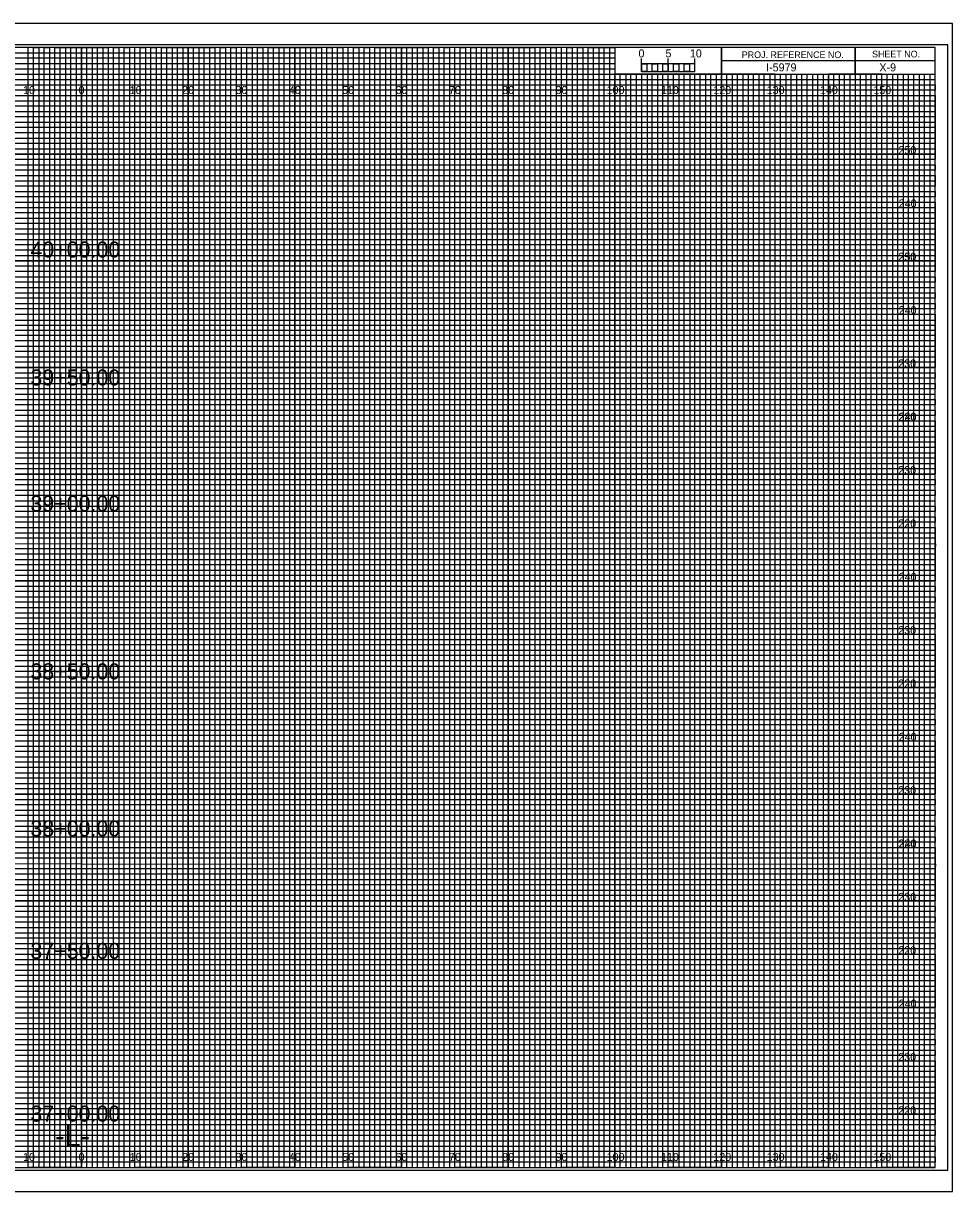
# Model space of a CAD drawing. Extents: x -13 to 359, y -5 to 2854.
# Drawn here: x 149.1 to 323.3, y 1755.5 to 1974.5 of the extents above; entities that cross this region are included whole.
import ezdxf

# ---------------------------------------------------------------- set-up
doc = ezdxf.new("R2010")
doc.units = 0
for name, color, linetype in [('Exist CMT Pavement', 7, 'Continuous'), ('Exist Cross Section Cell', 7, 'Continuous'), ('Exist XS Ground Line', 7, 'Continuous'), ('Prop CMT Conc Surface', 7, 'Continuous'), ('Prop CMT Concrete Structures', 7, 'Continuous'), ('Prop CMT DNC', 7, 'Continuous'), ('Prop CMT Pvmt Course 1', 7, 'Continuous'), ('Prop CMT Pvmt Course 1 CG', 7, 'Continuous'), ('Prop CMT Pvmt Course 1 Wedge', 7, 'Continuous'), ('Prop CMT Pvmt Course 2', 7, 'Continuous'), ('Prop CMT Pvmt Course 2 Wedge', 7, 'Continuous'), ('Prop CMT Pvmt Course 3', 7, 'Continuous'), ('Prop CMT Pvmt Course 3 Wedge', 7, 'Continuous'), ('Prop CMT Shear Line', 7, 'Continuous'), ('Prop CMT Slope Grass', 7, 'Continuous'), ('Prop CMT Subgrade Earthwork', 7, 'Continuous'), ('Scratch_Level_0', 7, 'Continuous')]:
    doc.layers.add(name, color=color, linetype=linetype)

msp = doc.modelspace()

# ---------------------------------------------------------------- linework, layer by layer
at = {"layer": 'Exist XS Ground Line'}
for p, q in [((150, 1970), (140, 1970)), ((150, 1760), (150, 1970)), ((170, 1970), (160, 1970)), ((160, 1970), (160, 1760)), ((170, 1760), (170, 1970)), ((190, 1970), (180, 1970)), ((180, 1970), (180, 1760)), ((190, 1760), (190, 1970)), ((210, 1970), (200, 1970)), ((200, 1970), (200, 1760)), ((210, 1760), (210, 1970)), ((230, 1970), (220, 1970)), ((220, 1970), (220, 1760)), ((230, 1760), (230, 1970)), ((250, 1970), (240, 1970)), ((240, 1970), (240, 1760)), ((250, 1760), (250, 1970)), ((260, 1970), (260, 1760)), ((270, 1760), (270, 1965)), ((290, 1965), (280, 1965)), ((280, 1965), (280, 1760)), ((290, 1760), (290, 1965)), ((310, 1965), (300, 1965)), ((300, 1965), (300, 1760)), ((310, 1760), (310, 1965)), ((160, 1760), (150, 1760)), ((180, 1760), (170, 1760)), ((200, 1760), (190, 1760)), ((220, 1760), (210, 1760)), ((240, 1760), (230, 1760)), ((260, 1760), (250, 1760)), ((280, 1760), (270, 1760)), ((300, 1760), (290, 1760)), ((320, 1760), (310, 1760)), ((320, 1760), (320, 1760))]:
    msp.add_line(p, q, dxfattribs=at)
for points in [[(0, 1960), (320, 1960), (320, 1950), (0, 1950)], [(0, 1940), (320, 1940), (320, 1930), (0, 1930)], [(0, 1920), (320, 1920), (320, 1910), (0, 1910)], [(0, 1900), (320, 1900), (320, 1890), (0, 1890)], [(0, 1880), (320, 1880), (320, 1870), (0, 1870)], [(0, 1860), (320, 1860), (320, 1850), (0, 1850)], [(0, 1840), (320, 1840), (320, 1830), (0, 1830)], [(0, 1820), (320, 1820), (320, 1810), (0, 1810)], [(0, 1800), (320, 1800), (320, 1790), (0, 1790)], [(0, 1780), (320, 1780), (320, 1770), (0, 1770)]]:
    msp.add_lwpolyline(points, dxfattribs=at)
at = {"layer": 'Prop CMT Conc Surface'}
for p, q in [((265, 1965.49), (265, 1967.9)), ((265, 1966.9), (265, 1967.9)), ((270, 1965.49), (270, 1967.9)), ((275, 1965.49), (275, 1967.9)), ((275, 1966.9), (275, 1967.9))]:
    msp.add_line(p, q, dxfattribs=at)
for points in [[(275, 1966.9), (265, 1966.9), (265, 1965.49), (275, 1965.49)], [(265, 1966.9), (266, 1966.9), (266, 1965.49), (265, 1965.49)], [(267, 1966.9), (268, 1966.9), (268, 1965.49), (267, 1965.49)], [(269, 1966.9), (270, 1966.9), (270, 1965.49), (269, 1965.49)], [(271, 1966.9), (272, 1966.9), (272, 1965.49), (271, 1965.49)], [(273, 1966.9), (274, 1966.9), (274, 1965.49), (273, 1965.49)]]:
    msp.add_lwpolyline(points, close=True, dxfattribs=at)
at = {"layer": 'Prop CMT Concrete Structures'}
for p, q in [((305, 1970), (305, 1965)), ((305, 1965), (305, 1970)), ((280, 1967.5), (280, 1965)), ((320, 1967.49), (280, 1967.49)), ((280, 1965), (320, 1965))]:
    msp.add_line(p, q, dxfattribs=at)
for points in [[(320, 1970), (0, 1970), (0, 1760), (320, 1760)], [(280, 1970), (260, 1970), (260, 1965.03), (280, 1965.03)], [(320, 1970), (280, 1970), (280, 1965), (320, 1965)]]:
    msp.add_lwpolyline(points, close=True, dxfattribs=at)
at = {"layer": 'Prop CMT DNC'}
for p, q in [((323.3, 1974.5), (-13.4, 1974.5)), ((-13.4, 1755.5), (323.3, 1755.5))]:
    msp.add_line(p, q, dxfattribs=at)
at = {"layer": 'Prop CMT Pvmt Course 1'}
for p, q in [((0, 1969), (260, 1969)), ((260, 1969), (260, 1967.98)), ((260, 1967.98), (0, 1967.98)), ((0, 1967), (260, 1967)), ((260, 1967), (260, 1965.89)), ((260, 1965.89), (0, 1965.89)), ((0, 1964), (320, 1964))]:
    msp.add_line(p, q, dxfattribs=at)
for points in [[(0, 1963), (270, 1963), (320, 1963), (320, 1962), (0, 1962)], [(0, 1961), (320, 1961), (320, 1959), (0, 1959)], [(0, 1958), (320, 1958), (320, 1957), (0, 1956.98)], [(0, 1956), (320, 1956), (320, 1954), (0, 1954)], [(0, 1953), (320, 1953), (320, 1952), (0, 1952)], [(0, 1951), (320, 1951), (320, 1949), (0, 1949)], [(0, 1948), (320, 1948), (320, 1947), (0, 1947)], [(0, 1946), (320, 1946), (320, 1944), (0, 1944)], [(0, 1943), (320, 1943), (320, 1942), (0, 1942)], [(0, 1941), (320, 1941), (320, 1939), (0, 1939)], [(0, 1938), (320, 1938), (320, 1937), (0, 1937)], [(0, 1936), (320, 1936), (320, 1933.95), (320, 1933), (320, 1932), (0, 1932)], [(0, 1934), (320, 1934), (320, 1933), (0, 1933)], [(0, 1931), (320, 1931), (320, 1929), (0, 1929.03)], [(0, 1929.03), (320, 1929), (320, 1928), (0, 1928)], [(0, 1927), (320, 1927), (320, 1926), (0, 1926)], [(0, 1924), (320, 1924), (320, 1923), (0, 1923)], [(0, 1922), (320, 1922), (320, 1921), (0, 1921)], [(-0.07, 1918.89), (320, 1918.89), (320, 1917.88), (-0.07, 1917.88)], [(0, 1917), (320, 1917), (320, 1916), (0, 1916)], [(0, 1914), (320, 1914), (320, 1913), (0, 1913)], [(0, 1912), (320, 1912), (320, 1911), (0, 1911)], [(0, 1909), (320, 1909), (320, 1908), (0, 1908)], [(0, 1907), (320, 1907), (320, 1906), (0, 1906)], [(0, 1904), (320, 1904), (320, 1903), (0, 1903)], [(0, 1902), (320, 1902), (320, 1901), (0, 1901)], [(0, 1899), (320, 1899), (319.99, 1897.98), (0, 1898)], [(0, 1897), (320, 1897), (320, 1896), (0, 1896)], [(0, 1894), (320, 1894), (320, 1893), (0, 1893)], [(0, 1892), (320, 1892), (320, 1891), (0, 1891)], [(0, 1889), (320, 1889), (320, 1888), (0, 1888)], [(0, 1887), (320, 1887), (320, 1886), (0, 1886)], [(0, 1884), (320, 1884), (320, 1883), (0, 1883)], [(0, 1882), (320, 1882), (320, 1881), (0, 1881)], [(0, 1879), (320, 1879), (320, 1878), (0, 1878)], [(0, 1876.99), (320.07, 1876.91), (320, 1876), (0, 1876)], [(0, 1874), (320, 1874), (320, 1873), (0, 1873)], [(0, 1872), (320, 1872), (320, 1871), (0, 1871)], [(0, 1869), (320, 1869), (320, 1868), (0, 1868)], [(0, 1867), (320, 1867), (320, 1866), (0, 1866)], [(0, 1864), (320, 1864), (320, 1863), (0, 1863)], [(0, 1862), (320, 1862), (320, 1861), (0, 1861)], [(0, 1859), (320, 1859), (320, 1858), (0, 1858)], [(0, 1857), (320, 1857), (320, 1856), (0, 1856)], [(0, 1854), (320, 1854), (320, 1853), (0, 1853)], [(0, 1852), (320, 1852), (320, 1851), (0, 1851)], [(0, 1849), (320, 1849), (320, 1848), (0, 1848)], [(0, 1847), (320, 1847), (320, 1846), (0, 1846)], [(0, 1844), (320, 1844), (320, 1843), (0, 1843)], [(0, 1842), (320, 1842), (320, 1841), (0, 1841)], [(0, 1839), (320, 1839), (319.99, 1837.98), (0, 1838)], [(0, 1837), (320, 1837), (320, 1836), (0, 1836)], [(0, 1834), (320, 1834), (320, 1833), (0, 1833)], [(0, 1832), (320, 1832), (320, 1831), (0, 1831)], [(0, 1829), (320, 1829), (320, 1828), (0, 1828)], [(0, 1827), (320, 1827), (320, 1826), (0, 1826)], [(0, 1824), (320, 1824), (320, 1823), (0, 1823)], [(0, 1822), (320, 1822), (320, 1821), (0, 1821)], [(0, 1819), (320, 1819), (320, 1818), (0, 1818)], [(0, 1816.99), (320.07, 1816.91), (320, 1816), (0, 1816)], [(0, 1814), (320, 1814), (320, 1813), (0, 1813)], [(0, 1812), (320, 1812), (320, 1811), (0, 1811)], [(0, 1809), (320, 1809), (320, 1808), (0, 1808)], [(0, 1807), (320, 1807), (320, 1806), (0, 1806)], [(0, 1804), (320, 1804), (320, 1803), (0, 1803)], [(0, 1802), (320, 1802), (320, 1801), (0, 1801)], [(0, 1799), (320, 1799), (320, 1798), (0, 1798)], [(0, 1797), (320, 1797), (320, 1796), (0, 1796)], [(0, 1794), (320, 1794), (320, 1793), (0, 1793)], [(0, 1792), (320, 1792), (320, 1791), (0, 1791)], [(0, 1789), (320, 1789), (320, 1788), (0, 1788)], [(0, 1787), (320, 1787), (320, 1786), (0, 1786)], [(0, 1784), (320, 1784), (320, 1783), (0, 1783)], [(0, 1782), (320, 1782), (320, 1781), (0, 1781)], [(0, 1779), (320, 1779), (320, 1778), (0, 1778)], [(0, 1777), (320, 1777), (320, 1776), (0, 1776)], [(0, 1774), (320, 1774), (320, 1773), (0, 1773)], [(0, 1772), (320, 1772), (320, 1771), (0, 1771)], [(0, 1769), (320, 1769), (320, 1768), (0, 1768)], [(0, 1767), (320, 1767), (320, 1766), (0, 1766)], [(0, 1764), (320, 1764), (320, 1763), (0, 1763)], [(0, 1762), (320, 1762), (320, 1761), (0, 1761)]]:
    msp.add_lwpolyline(points, dxfattribs=at)
at = {"layer": 'Prop CMT Pvmt Course 1 CG'}
for p, q in [((267, 1965), (266.01, 1965)), ((266.01, 1965), (266.01, 1760)), ((267, 1760), (267, 1965)), ((269, 1965), (268, 1965)), ((268, 1965), (268, 1760)), ((269, 1760), (269, 1965)), ((266.01, 1760), (265, 1760)), ((268, 1760), (267, 1760))]:
    msp.add_line(p, q, dxfattribs=at)
for points in [[(150, 1760), (151, 1760), (151, 1970), (152, 1970), (152, 1760)], [(152, 1760), (153, 1760), (153, 1970), (154, 1970), (154, 1760)], [(155, 1760), (156, 1760), (156, 1970), (157, 1970), (157, 1760)], [(157, 1760), (158, 1760), (158, 1970), (159, 1970), (159, 1760)], [(160, 1760), (161, 1760), (161, 1970), (162, 1970), (162, 1760)], [(162, 1760), (163, 1760), (163, 1970), (164, 1970), (164, 1760)], [(165, 1760), (166, 1760), (166, 1970), (167, 1970), (167, 1760)], [(167, 1760), (168, 1760), (168, 1970), (169, 1970), (169, 1760)], [(170, 1760), (171, 1760), (171, 1970), (172, 1970), (172, 1760)], [(172, 1760), (173, 1760), (173, 1970), (174, 1970), (174, 1760)], [(175, 1760), (176, 1760), (176, 1970), (177, 1970), (177, 1760)], [(177, 1760), (178, 1760), (178, 1970), (179, 1970), (179, 1760)], [(180, 1760), (181, 1760), (181, 1970), (182, 1970), (182, 1760)], [(182, 1760), (183, 1760), (183, 1970), (184, 1970), (184, 1760)], [(185, 1760), (186, 1760), (186, 1970), (187, 1970), (187, 1760)], [(187, 1760), (188, 1760), (188, 1970), (189, 1970), (189, 1760)], [(190, 1760), (191, 1760), (191, 1970), (192, 1970), (192, 1760)], [(192, 1760), (193, 1760), (193, 1970), (194, 1970), (194, 1760)], [(195, 1760), (196, 1760), (196, 1970), (197, 1970), (197, 1760)], [(197, 1760), (198, 1760), (198, 1970), (199, 1970), (199, 1760)], [(200, 1760), (201, 1760), (201, 1970), (202, 1970), (202, 1760)], [(202, 1760), (203, 1760), (203, 1970), (204, 1970), (204, 1760)], [(205, 1760), (206, 1760), (206, 1970), (207, 1970), (207, 1760)], [(207, 1760), (208, 1760), (208, 1970), (209, 1970), (209, 1760)], [(210, 1760), (211, 1760), (211, 1970), (212, 1970), (212, 1760)], [(212, 1760), (213, 1760), (213, 1970), (214, 1970), (214, 1760)], [(215, 1760), (216, 1760), (216, 1970), (217, 1970), (217, 1760)], [(217, 1760), (218, 1760), (218, 1970), (219, 1970), (219, 1760)], [(220, 1760), (221, 1760), (221, 1970), (222, 1970), (222, 1760)], [(222, 1760), (223, 1760), (223, 1970), (224, 1970), (224, 1760)], [(225, 1760), (226, 1760), (226, 1970), (227, 1970), (227, 1760)], [(227, 1760), (228, 1760), (228, 1970), (229, 1970), (229, 1760)], [(230, 1760), (231, 1760), (231, 1970), (232, 1970), (232, 1760)], [(232, 1760), (233, 1760), (233, 1970), (234, 1970), (234, 1760)], [(235, 1760), (236, 1760), (236, 1970), (237, 1970), (237, 1760)], [(237, 1760), (238, 1760), (238, 1970), (239, 1970), (239, 1760)], [(240, 1760), (241, 1760), (241, 1970), (242, 1970), (242, 1760)], [(242, 1760), (243, 1760), (243, 1970), (244, 1970), (244, 1760)], [(245, 1760), (246, 1760), (246, 1970), (247, 1970), (247, 1760)], [(247, 1760), (248, 1760), (248, 1970), (249, 1970), (249, 1760)], [(250, 1760), (251, 1760), (251, 1970), (252, 1970), (252, 1760)], [(252, 1760), (253, 1760), (253, 1970), (254, 1970), (254, 1760)], [(255, 1760), (256, 1760), (256, 1970), (257, 1970), (257, 1760)], [(257, 1760), (258, 1760), (258, 1970), (259, 1970), (259, 1760)], [(260, 1760), (261, 1760), (261, 1965), (262.02, 1965), (262.02, 1760)], [(262, 1760), (263, 1760), (263, 1965), (263.99, 1965), (263.99, 1760)], [(270, 1760), (270.98, 1760), (270.98, 1965), (272, 1965), (272, 1760)], [(272, 1760), (273, 1760), (273, 1965), (274.05, 1965), (274.05, 1760)], [(275, 1760), (276, 1760), (276, 1965), (277, 1965), (277, 1760)], [(277, 1760), (278, 1760), (278, 1965), (279, 1965), (279, 1760)], [(280, 1760), (281, 1760), (281, 1965), (282, 1965), (282, 1760)], [(282, 1760), (283, 1760), (283, 1965), (284, 1965), (284, 1760)], [(285, 1760), (286, 1760), (286, 1965), (287, 1965), (287, 1760)], [(287, 1760), (288, 1760), (288, 1965), (289, 1965), (289, 1760)], [(290, 1760), (291, 1760), (291, 1965), (292, 1965), (292, 1760)], [(292, 1760), (293, 1760), (293, 1965), (294, 1965), (294, 1760)], [(295, 1760), (296, 1760), (296, 1965), (297, 1965), (297, 1760)], [(297, 1760), (298, 1760), (298, 1965), (299, 1965), (299, 1760)], [(300, 1760), (301, 1760), (301, 1965), (302, 1965), (302, 1760)], [(302, 1760), (303, 1760), (303, 1965), (304, 1965), (304, 1760)], [(305, 1760), (306, 1760), (306, 1965), (307, 1965), (307, 1760)], [(307, 1760), (308, 1760), (308, 1965), (309, 1965), (309, 1760)], [(310, 1760), (311, 1760), (311, 1965), (312, 1965), (312, 1760)], [(312, 1760), (313, 1760), (313, 1965), (314, 1965), (314, 1760)], [(315, 1760), (316, 1760), (316, 1965), (317, 1965), (317, 1760)], [(317, 1760), (318, 1760), (318, 1965), (319, 1965), (319, 1760)]]:
    msp.add_lwpolyline(points, dxfattribs=at)
at = {"layer": 'Prop CMT Shear Line'}
for p, q in [((150, 1760), (150, 1970)), ((160, 1760), (160, 1970)), ((170, 1760), (170, 1970)), ((180, 1760), (180, 1970)), ((190, 1760), (190, 1970)), ((200, 1760), (200, 1970)), ((210, 1760), (210, 1970)), ((220, 1760), (220, 1970)), ((230, 1760), (230, 1970)), ((240, 1760), (240, 1970)), ((250, 1760), (250, 1970)), ((260, 1760), (260, 1964.69)), ((270, 1760), (270, 1964.69)), ((280, 1760), (280, 1964.69)), ((290, 1760), (290, 1964.69)), ((300, 1760), (300, 1964.69)), ((310, 1760), (310, 1964.69)), ((0, 1960), (320, 1960)), ((0, 1950), (320, 1950)), ((0, 1940), (320, 1940)), ((0, 1930), (320, 1930)), ((0, 1920), (320, 1920)), ((0, 1910), (320, 1910)), ((0, 1900), (320, 1900)), ((0, 1890), (320, 1890)), ((0, 1880), (320, 1880)), ((0, 1870), (320, 1870)), ((0, 1860), (320, 1860)), ((0, 1850), (320, 1850)), ((0, 1840), (320, 1840)), ((0, 1830), (320, 1830)), ((0, 1820), (320, 1820)), ((0, 1810), (320, 1810)), ((0, 1800), (320, 1800)), ((0, 1790), (320, 1790)), ((0, 1780), (320, 1780)), ((0, 1770), (320, 1770))]:
    msp.add_line(p, q, dxfattribs=at)
at = {"layer": 'Prop CMT Slope Grass'}
msp.add_lwpolyline([(-10.8, 1759.5), (322.4, 1759.5), (322.4, 1970.5), (-10.8, 1970.5)], close=True, dxfattribs=at)
at = {"layer": 'Prop CMT Subgrade Earthwork'}
msp.add_lwpolyline([(-13.4, 1755.5), (323.3, 1755.5), (323.3, 1974.5), (-13.4, 1974.5)], close=True, dxfattribs=at)
at = {"layer": 'Scratch_Level_0'}
for points in [[(145, 1760), (155, 1760), (155, 1970), (165, 1970), (165, 1760), (175, 1760), (175, 1970), (185, 1970), (185, 1760), (195, 1760), (195, 1970), (205, 1970), (205, 1760), (215, 1760), (215, 1970), (225, 1970), (225, 1760), (235, 1760), (235, 1970), (245, 1970), (245, 1760), (255, 1760), (255, 1970), (259.93, 1970), (260, 1970), (260, 1965), (264.99, 1965), (264.99, 1760), (275, 1760), (275, 1965), (285, 1965), (285, 1760), (295, 1760), (295, 1965), (305, 1965), (305, 1760), (315, 1760), (315, 1965)], [(0, 1965), (275, 1965)], [(0, 1945), (320, 1945), (320, 1955), (0, 1955)], [(0, 1925), (320, 1925), (320, 1935), (0, 1935)], [(0, 1905), (320, 1905), (320, 1915), (0, 1915)], [(0, 1885), (320, 1885), (320, 1895), (0, 1895)], [(0, 1865), (320, 1865), (320, 1875), (0, 1875)], [(0, 1845), (320, 1845), (320, 1855), (0, 1855)], [(0, 1825), (320, 1825), (320, 1835), (0, 1835)], [(0, 1805), (320, 1805), (320, 1815), (0, 1815)], [(0, 1785), (320, 1785), (320, 1795), (0, 1795)], [(0, 1765), (320, 1765), (320, 1775), (0, 1775)]]:
    msp.add_lwpolyline(points, dxfattribs=at)

# ---------------------------------------------------------------- texts
at = {"layer": 'Exist CMT Pavement'}
for s, p in [('5', (269.47, 1968.12)), ('10', (274.04, 1968.12))]:
    msp.add_text(s, height=1.5, dxfattribs=at).set_placement(p)
at = {"layer": 'Exist Cross Section Cell'}
for s, p in [('10', (149.04, 1961.25)), ('0', (159.45, 1961.25)), ('0', (159.45, 1961.25)), ('10', (169.04, 1961.25)), ('20', (178.86, 1961.25)), ('30', (188.86, 1961.25)), ('40', (198.86, 1961.25)), ('50', (208.86, 1961.25)), ('60', (218.86, 1961.25)), ('70', (228.86, 1961.25)), ('80', (238.86, 1961.25)), ('90', (248.86, 1961.25)), ('100', (258.44, 1961.25)), ('110', (268.62, 1961.25)), ('120', (278.44, 1961.25)), ('130', (288.44, 1961.25)), ('140', (298.44, 1961.25)), ('150', (308.44, 1961.25)), ('10', (149.04, 1761.25)), ('0', (159.45, 1761.25)), ('0', (159.45, 1761.25)), ('10', (169.04, 1761.25)), ('20', (178.86, 1761.25)), ('30', (188.86, 1761.25)), ('40', (198.86, 1761.25)), ('50', (208.86, 1761.25)), ('60', (218.86, 1761.25)), ('70', (228.86, 1761.25)), ('80', (238.86, 1761.25)), ('90', (248.86, 1761.25)), ('100', (258.44, 1761.25)), ('110', (268.62, 1761.25)), ('120', (278.44, 1761.25)), ('130', (288.44, 1761.25)), ('140', (298.44, 1761.25)), ('150', (308.44, 1761.25))]:
    msp.add_text(s, height=1.5, dxfattribs=at).set_placement(p)
at = {"layer": 'Prop CMT Conc Surface'}
msp.add_text('0', height=1.5, dxfattribs=at).set_placement((264.41, 1968.12))
at = {"layer": 'Prop CMT Concrete Structures'}
for s, p in [('PROJ. REFERENCE NO.', (283.77, 1967.99)), ('SHEET NO.', (308.19, 1968.12))]:
    msp.add_text(s, height=1.25, dxfattribs=at).set_placement(p)
at = {"layer": 'Prop CMT Pvmt Course 1 Wedge'}
msp.add_text('X-9', height=1.5, dxfattribs=at).set_placement((309.57, 1965.5))
at = {"layer": 'Prop CMT Pvmt Course 2'}
for s, p in [('250', (313.15, 1950)), ('240', (313.19, 1940)), ('230', (313.11, 1930)), ('250', (313.15, 1930)), ('240', (313.19, 1920)), ('230', (313.11, 1910)), ('220', (313.12, 1900)), ('240', (313.19, 1900)), ('230', (313.11, 1890)), ('220', (313.12, 1880)), ('240', (313.19, 1870)), ('230', (313.11, 1860)), ('220', (313.12, 1850)), ('240', (313.19, 1840)), ('230', (313.11, 1830)), ('220', (313.12, 1820)), ('240', (313.19, 1820)), ('230', (313.11, 1810)), ('220', (313.12, 1800)), ('240', (313.19, 1790)), ('230', (313.11, 1780)), ('220', (313.12, 1770))]:
    msp.add_text(s, height=1.5, dxfattribs=at).set_placement(p)
at = {"layer": 'Prop CMT Pvmt Course 2 Wedge'}
msp.add_text('I-5979', height=1.5, dxfattribs=at).set_placement((288.34, 1965.5))
at = {"layer": 'Prop CMT Pvmt Course 3'}
for s, p in [('40+00.00', (150.41, 1930.6)), ('39+50.00', (150.41, 1906.62)), ('39+00.00', (150.41, 1882.99)), ('38+50.00', (150.41, 1851.53)), ('38+00.00', (150.41, 1822.09)), ('37+50.00', (150.41, 1799.14)), ('37+00.00', (150.41, 1768.62))]:
    msp.add_text(s, height=3, dxfattribs=at).set_placement(p)
at = {"layer": 'Prop CMT Pvmt Course 3 Wedge'}
msp.add_text('-L-', height=4, dxfattribs=at).set_placement((155.06, 1764))

doc.saveas('drawing.dxf')
